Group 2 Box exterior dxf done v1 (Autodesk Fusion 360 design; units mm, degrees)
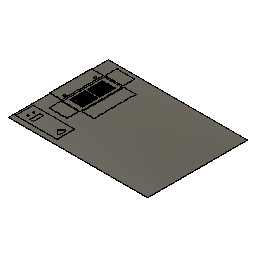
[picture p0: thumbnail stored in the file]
sketch "草图1" plane through (0, 0, 0) normal (0, 0, 1) x axis (1, 0, 0)
  line L1 (-60, 148.5) -> (60, 148.5)
  line L2 (-60, -148.5) -> (-60, 148.5)
  line L3 (60, -148.5) -> (-60, -148.5)
  line L4 (60, 148.5) -> (60, -148.5)
  line L5 (-60, -148.5) -> (60, 148.5)
  line L6 (60, -148.5) -> (-60, 148.5)
  line L7 (-63, 151.5) -> (63, 151.5)
  line L8 (-63, -151.5) -> (-63, 151.5)
  line L9 (63, -151.5) -> (-63, -151.5)
  line L10 (63, 151.5) -> (63, -151.5)
  point P6 (0, 0)
  point P1 (0, 0)
  point P4 (-60, -148.5)
  point P5 (60, -148.5)
  point P3 (-60, 148.5)
  horizontal L1
  perpendicular L1 L2
  parallel L1 L3
  parallel L2 L4
  coincident L5 P6
  coincident L6 P6
  coincident P1 P6
  dimension "d1" distance P4 P5 = 120
  dimension "d2" distance P3 P4 = 297
  dimension "d3" = 3
extrude "拉伸1" new body sketch "草图1" profile of L1 L2 L3 L4 L7 L8 L9 L10 along normal blind 83
sketch "草图2" plane through (0, 0, 0) normal (0, 0, 1) x axis (1, 0, 0)
  line L1 (-63, -151.5) -> (63, -151.5)
  line L2 (-63, 151.5) -> (-63, -151.5)
  line L3 (63, 151.5) -> (-63, 151.5)
  line L4 (63, -151.5) -> (63, 151.5)
  horizontal L1
  vertical L2
  horizontal L3
  vertical L4
extrude "拉伸2" add sketch "草图2" against normal blind 3
sketch "草图1" plane through (0, 0, 0) normal (0, 0, 1) x axis (1, 0, 0)
  line L1 (-60, -151.5) -> (63, -151.5)
  line L2 (-62.9999, 151.5267) -> (-62.9999, -151.5)
  line L3 (63, 151.5267) -> (-59.9999, 151.5267)
  line L4 (63, -9.9866) -> (64, -9.9866)
  line L5 (64, 10.0134) -> (63, 10.0134)
  line L6 (66, -7.9866) -> (66, 8.0134)
  line L7 (60, 10.0134) -> (66, -9.9866)
  line L8 (66, 10.0134) -> (60, -9.9866)
  line L9 (63, 10.0134) -> (63, 151.5267)
  line L10 (63, -151.5) -> (63, -9.9866)
  line L11 (-59.9999, 156.5267) -> (-59.9999, 151.5267)
  line L12 (-62.9999, 156.5267) -> (-59.9999, 156.5267)
  line L13 (-62.9999, 151.5267) -> (-62.9999, 156.5267)
  line L14 (-62.9999, -151.5) -> (-63, -151.5)
  line L15 (-60, -156.5) -> (-60, -151.5)
  line L16 (-63, -156.5) -> (-60, -156.5)
  line L17 (-63, -151.5) -> (-63, -156.5)
  arc A1 centre (64, -7.9866) radius 2 clockwise from (66, -7.9866) to (64, -9.9866)
  arc A2 centre (64, 8.0134) radius 2 clockwise from (64, 10.0134) to (66, 8.0134)
  point P6 (66, -9.9866)
  point P9 (66, 10.0134)
  point P16 (63, -9.9866)
  point P8 (60, 10.0134)
  point P7 (60, -9.9866)
  point P4 (-62.9999, 151.5267)
  point P18 (-59.9999, 151.5267)
  point P20 (-62.9999, 156.5267)
  point P21 (-63, -151.5)
  point P22 (-60, -151.5)
  point P24 (-63, -156.5)
  horizontal L1
  vertical L2
  horizontal L3
  vertical L9
  horizontal L4
  parallel L4 L5
  coincident P6 L4
  coincident P6 L6
  tangent L4 A1
  tangent L6 A1
  coincident P9 L6
  coincident P9 L5
  tangent L6 A2
  tangent L5 A2
  coincident P16 L9
  collinear L9 L10
  vertical L11
  horizontal L12
  vertical L13
  horizontal L14
  vertical L15
  horizontal L16
  vertical L17
  dimension "d8" distance P8 P9 = 6
  dimension "d9" distance P7 P8 = 20
  dimension "d10" radius A1 = 2
  dimension "d11" radius A2 = 2
  dimension "d12" distance P4 P18 = 3
  dimension "d13" distance P4 P20 = 5
  dimension "d14" distance P21 P22 = 3
  dimension "d15" distance P21 P24 = 5
extrude "拉伸1" new body sketch "草图1" profile of L1 L2 L3 L10 L4 L5 L6 A1 A2 L11 L12 L13 L14 L15 L16 L17 along normal blind 3
move "移动1"
component_from_bodies "实体->零部件"
sketch "草图2" plane through (0, 0, 65) normal (0, 0, -1) x axis (1, 0, 0)
  line L1 (63, 9.9866) -> (64, 9.9866)
  line L2 (63, 151.5) -> (63, 9.9866)
  line L3 (-60, 151.5) -> (63, 151.5)
  line L4 (-60, 156.5) -> (-60, 151.5)
  line L5 (-63, 156.5) -> (-60, 156.5)
  line L6 (-63, 151.5) -> (-63, 156.5)
  line L7 (-62.9999, 151.5) -> (-63, 151.5)
  line L8 (-62.9999, -156.5267) -> (-62.9999, 151.5)
  line L9 (-59.9999, -156.5267) -> (-62.9999, -156.5267)
  line L10 (-59.9999, -151.5267) -> (-59.9999, -156.5267)
  line L11 (63, -151.5267) -> (-59.9999, -151.5267)
  line L12 (63, -10.0134) -> (63, -151.5267)
  line L13 (64, -10.0134) -> (63, -10.0134)
  line L14 (66, 7.9866) -> (66, -8.0134)
  arc A1 centre (64, 7.9866) radius 2 clockwise from (64, 9.9866) to (66, 7.9866)
  arc A2 centre (64, -8.0134) radius 2 clockwise from (66, -8.0134) to (64, -10.0134)
sketch "草图3" plane through (0, 0, 0) normal (0, 0, 1) x axis (1, 0, 0)
  line L1 (-1.3407, -91.6748) -> (-29.625, -119.959)
  line L2 (-1.3407, -91.6748) -> (26.9436, -119.959)
  arc A1 centre (-1.3407, -91.6748) radius 40 clockwise from (26.9436, -119.959) to (-29.625, -119.959)
  perpendicular L1 L2
  dimension "d19" diameter A1 = 80
split "分割1"
sketch "草图4" plane through (0, 0, 0) normal (0, 0, 1) x axis (1, 0, 0)
  line L1 (36.5, 73) -> (-36.5, 73)
  line L2 (36.5, 47) -> (36.5, 73)
  line L3 (-36.5, 47) -> (36.5, 47)
  line L4 (-36.5, 73) -> (-36.5, 47)
  line L5 (36.5, 47) -> (-36.5, 73)
  line L6 (-36.5, 47) -> (36.5, 73)
  circle C1 centre (20.9238, 102.4465) radius 6
  circle C2 centre (-20.0762, 102.4465) radius 6
  point P6 (0, 60)
  point P4 (36.5, 47)
  point P5 (-36.5, 47)
  point P3 (36.5, 73)
  horizontal L1
  perpendicular L1 L2
  parallel L1 L3
  parallel L2 L4
  coincident L5 P6
  coincident L6 P6
  dimension "d22" distance P4 P5 = 73
  dimension "d23" distance P3 P4 = 26
  dimension "d24" diameter C1 = 12
  dimension "d25" diameter C2 = 12
extrude "拉伸3" new body sketch "草图4" profile of L1 L2 L3 L4 C1 C2 along normal blind 5
move "移动3"
ground "地面1"
move "移动4"
split "分割2"
split "分割3"
ground "地面2"
hole "孔1" HoleDepth 15 HoleDiameter 15 TipAngle 118
remove_body "移除实体1"
remove_body "移除实体2"
remove_body "移除实体3"
ground "地面3"
sketch "草图3" plane through (63, 0, 0) normal (1, 0, 0) x axis (0, 1, 0)
  line L1 (151.5, 83) -> (151.5, 0)
  line L2 (-151.5, 83) -> (151.5, 83)
  line L3 (-151.5, -3) -> (-151.5, 83)
  line L4 (151.5, -3) -> (-151.5, -3)
  line L5 (151.5, 0) -> (151.5, -3)
  line L6 (-9, 80) -> (9, 80)
  line L7 (-10, 83) -> (-10, 81)
  line L8 (10, 81) -> (10, 83)
  arc A1 centre (-9, 81) radius 1 clockwise from (-9, 80) to (-10, 81)
  arc A2 centre (9, 81) radius 1 clockwise from (10, 81) to (9, 80)
  point P7 (0, 83)
  point P14 (-10, 83)
  point P15 (10, 83)
  horizontal L6
  perpendicular L6 L7
  parallel L7 L8
  midpoint L2 P7
  tangent L7 A1
  tangent L6 A1
  tangent L6 A2
  tangent L8 A2
  equal A1 A2
  coincident L2 P14
  coincident L2 P15
  dimension "d36" radius A1 = 1
ground "地面4"
position "位置"
extrude "拉伸3" cut sketch "草图3" profile of L2 L6 L7 L8 A1 A2 against normal blind 5
offset_faces "偏移面1" distance 3
offset_faces "偏移面2" distance -3
offset_faces "偏移面1" distance -3
offset_faces "偏移面2" distance -3
offset_faces "偏移面3" distance -3
offset_faces "偏移面4" distance -3
offset_faces "偏移面3" distance 3
offset_faces "偏移面4" distance -3
sketch "草图4" plane through (0, 0, 83) normal (0, 0, 1) x axis (-1, 0, 0)
  line L1 (-63, 10) -> (-66, 10)
  line L2 (-63, 148.5) -> (-63, 10)
  line L3 (63, 148.5) -> (-63, 148.5)
  line L4 (63, -148.5) -> (63, 148.5)
  line L5 (-63, -148.5) -> (63, -148.5)
  line L6 (-63, -10) -> (-63, -148.5)
  line L7 (-66, -10) -> (-63, -10)
  line L8 (-66, -151.5) -> (-66, -10)
  line L9 (66, -151.5) -> (-66, -151.5)
  line L10 (66, 151.5) -> (66, -151.5)
  line L11 (-66, 151.5) -> (66, 151.5)
  line L12 (-66, 10) -> (-66, 151.5)
  line L13 (57.0003, -151.5) -> (59.9995, -151.5)
  line L14 (57.0003, -148.5275) -> (57.0003, -151.5)
  line L15 (59.9995, -148.5275) -> (57.0003, -148.5275)
  line L16 (59.9995, -151.5) -> (59.9995, -148.5275)
  point P14 (59.9995, -151.5)
  horizontal L13
  vertical L14
  horizontal L15
  vertical L16
  coincident L9 P14
extrude "拉伸4" add sketch "草图4" profile of L9 L13 L14 L15 L16 along normal blind 6.1
sketch "草图5" plane through (-59.9995, 0, 0) normal (-1, 0, 0) x axis (0, -1, 0)
  line L1 (-148.5275, 83) -> (-151.5, 83)
  line L2 (-148.5275, 89.1) -> (-148.5275, 83)
  line L3 (-151.5, 89.1) -> (-148.5275, 89.1)
  line L4 (-151.5, 83) -> (-151.5, 89.1)
  line L5 (-148.5275, 89.1) -> (-151.5, 89.1)
  line L6 (-148.5275, 86.05) -> (-148.5275, 89.1)
  line L7 (-151.5, 86.05) -> (-148.5275, 86.05)
  line L8 (-151.5, 89.1) -> (-151.5, 86.05)
  point P8 (-148.5275, 86.05)
  point P5 (-151.5, 89.1)
  point P6 (-151.5, 89.1)
  horizontal L5
  vertical L6
  horizontal L7
  vertical L8
  midpoint L2 P8
  coincident P5 P6
extrude "拉伸5" add sketch "草图5" profile of L2 L3 L4 L5 L6 L7 L8 along normal blind 6
sketch "草图6" plane through (0, 0, 83) normal (0, 0, 1) x axis (-1, 0, 0)
  line L1 (57.0003, -148.5275) -> (57.0003, -151.5)
  line L2 (59.9995, -148.5275) -> (57.0003, -148.5275)
  line L3 (59.9995, -151.5) -> (59.9995, -148.5275)
  line L4 (66, -151.5) -> (59.9995, -151.5)
  line L5 (66, 151.5) -> (66, -151.5)
  line L6 (-66, 151.5) -> (66, 151.5)
  line L7 (-66, 10) -> (-66, 151.5)
  line L8 (-63, 10) -> (-66, 10)
  line L9 (-63, 148.5) -> (-63, 10)
  line L10 (63, 148.5) -> (-63, 148.5)
  line L11 (63, -148.5) -> (63, 148.5)
  line L12 (-63, -148.5) -> (63, -148.5)
  line L13 (-63, -10) -> (-63, -148.5)
  line L14 (-66, -10) -> (-63, -10)
  line L15 (-66, -151.5) -> (-66, -10)
  line L16 (57.0003, -151.5) -> (-66, -151.5)
  line L17 (63, -151.5) -> (66, -151.5)
  line L18 (63, -148.5) -> (63, -151.5)
  line L19 (66, -148.5) -> (63, -148.5)
  line L20 (66, -151.5) -> (66, -148.5)
  point P6 (66, -151.5)
  point P18 (66, -151.5)
  point P19 (63, -151.5)
  point P21 (66, -148.5)
  horizontal L17
  vertical L18
  horizontal L19
  vertical L20
  coincident P6 P18
  dimension "d51" distance P18 P19 = 3
  dimension "d52" distance P18 P21 = 3
extrude "拉伸6" add sketch "草图6" profile of L4 L5 L17 L18 L19 L20 along normal blind 3
sketch "草图7" plane through (0, 0, 83) normal (0, 0, 1) x axis (-1, 0, 0)
  line L1 (66, -148.5) -> (63, -148.5)
  line L2 (66, 151.5) -> (66, -148.5)
  line L3 (-66, 151.5) -> (66, 151.5)
  line L4 (-66, 10) -> (-66, 151.5)
  line L5 (-63, 10) -> (-66, 10)
  line L6 (-63, 148.5) -> (-63, 10)
  line L7 (63, 148.5) -> (-63, 148.5)
  line L8 (63, -148.5) -> (63, 148.5)
  line L9 (57, 148.5) -> (66, 148.5)
  line L10 (57, 151.5) -> (57, 148.5)
  line L11 (66, 151.5) -> (57, 151.5)
  line L12 (66, 148.5) -> (66, 151.5)
  point P10 (66, 148.5)
  point P11 (57, 148.5)
  horizontal L9
  vertical L10
  horizontal L11
  vertical L12
  coincident L2 P10
  dimension "d55" distance P10 P11 = 9
extrude "拉伸7" add sketch "草图7" profile of L2 L3 L7 L9 L10 L11 L12 along normal blind 6
sketch "草图8" plane through (0, -151.5, 0) normal (0, -1, 0) x axis (1, 0, 0)
  line L1 (66, 83) -> (66, -3)
  line L2 (-57, 83) -> (66, 83)
  line L3 (-57, 89) -> (-57, 83)
  line L4 (-66, 89) -> (-57, 89)
  line L5 (-66, -3) -> (-66, 89)
  line L6 (66, -3) -> (-66, -3)
  circle C1 centre (-61.5, 81.5) radius 2.15
  dimension "d58" diameter C1 = 4.3
extrude "拉伸1" cut sketch "草图8" profile of C1 along normal blind 38
extrude "拉伸8" cut sketch "草图8" profile of C1 against normal blind 318
hole "孔1" HoleDepth 27.5 HoleDiameter 15 TipAngle 118 CBDepth 25 CBDiameter 16.5
hole "孔2" HoleDepth 27.5 HoleDiameter 15 TipAngle 118 CBDepth 1 CBDiameter 16.5
offset_faces "偏移面5" distance 3
sketch "草图9" plane through (0, 0, -3) normal (0, 0, -1) x axis (1, 0, 0)
  line L1 (66, -151.5) -> (-66, -151.5)
  line L2 (66, 151.5) -> (66, -151.5)
  line L3 (-66, 151.5) -> (66, 151.5)
  line L4 (-66, -151.5) -> (-66, 151.5)
  line L5 (-36, -151.5) -> (-66, -151.5)
  line L6 (-36, -148.5) -> (-36, -151.5)
  line L7 (-66, -148.5) -> (-36, -148.5)
  line L8 (-66, -151.5) -> (-66, -148.5)
  line L9 (36, -151.5) -> (66, -151.5)
  line L10 (36, -148.5) -> (36, -151.5)
  line L11 (66, -148.5) -> (36, -148.5)
  line L12 (66, -151.5) -> (66, -148.5)
  line L13 (-14, -151.5) -> (10.9264, -151.5)
  line L14 (-14, -148.5) -> (-14, -151.5)
  line L15 (10.9264, -148.5) -> (-14, -148.5)
  line L16 (10.9264, -151.5) -> (10.9264, -148.5)
  point P2 (-66, -151.5)
  point P6 (-66, -151.5)
  point P3 (66, -151.5)
  point P10 (66, -151.5)
  point P7 (-36, -151.5)
  point P9 (-66, -148.5)
  point P11 (36, -151.5)
  point P13 (66, -148.5)
  horizontal L5
  vertical L6
  horizontal L7
  vertical L8
  coincident P2 P6
  horizontal L9
  vertical L10
  horizontal L11
  vertical L12
  coincident P3 P10
  horizontal L13
  vertical L14
  horizontal L15
  vertical L16
  dimension "d74" distance P6 P7 = 30
  dimension "d75" distance P6 P9 = 3
  dimension "d76" distance P10 P11 = 30
  dimension "d77" distance P10 P13 = 3
sketch "草图10" plane through (66, 0, 0) normal (1, 0, 0) x axis (0, 1, 0)
  line L1 (-10, 83) -> (-10, 81)
  line L2 (-151.5, -3) -> (-151.5, 83)
  line L3 (151.5, -3) -> (-151.5, -3)
  line L4 (151.5, 83) -> (151.5, -3)
  line L5 (10, 83) -> (151.5, 83)
  line L6 (10, 81) -> (10, 83)
  line L7 (-9, 80) -> (9, 80)
  line L8 (-148.5, 92) -> (-148.5, 83)
  arc A1 centre (9, 81) radius 1 clockwise from (10, 81) to (9, 80)
  arc A2 centre (-9, 81) radius 1 clockwise from (-9, 80) to (-10, 81)
  point P4 (-151.5, 83)
  point P14 (-148.5, 83)
  vertical L8
  dimension "d79" distance P4 P14 = 3
split "分割1"
sketch "草图11" plane through (66, 0, 0) normal (1, 0, 0) x axis (0, 1, 0)
  line L1 (-148.5, -3) -> (-148.5, 83)
  line L2 (151.5, -3) -> (-148.5, -3)
  line L3 (151.5, 83) -> (151.5, -3)
  line L4 (10, 83) -> (151.5, 83)
  line L5 (10, 81) -> (10, 83)
  line L6 (-9, 80) -> (9, 80)
  line L7 (-10, 83) -> (-10, 81)
  line L8 (-148.5, 83) -> (-10, 83)
  line L9 (148.5, 93) -> (148.5, 83)
  arc A1 centre (9, 81) radius 1 clockwise from (10, 81) to (9, 80)
  arc A2 centre (-9, 81) radius 1 clockwise from (-9, 80) to (-10, 81)
  point P5 (151.5, 83)
  point P14 (148.5, 83)
  vertical L9
  dimension "d81" distance P5 P14 = 3
split "分割2"
sketch "草图12" plane through (0, -148.5, 0) normal (0, -1, 0) x axis (1, 0, 0)
  line L1 (66, -3) -> (-66, -3)
  line L2 (66, 83) -> (66, -3)
  line L3 (63, 83) -> (66, 83)
  line L4 (63, 0) -> (63, 83)
  line L5 (-63, 0) -> (63, 0)
  line L6 (-63, 79.9597) -> (-63, 0)
  line L7 (-66, 83) -> (-63.0403, 83)
  line L8 (-66, -3) -> (-66, 83)
  line L9 (-66, 0) -> (-73, 0)
  arc A1 centre (-61.5, 81.5) radius 2.15 clockwise from (-63, 79.9597) to (-63.0403, 83)
  point P2 (-66, -3)
  point P13 (-66, 0)
  horizontal L9
  dimension "d84" distance P2 P13 = 3
split "分割3"
sketch "草图13" plane through (0, 0, 0) normal (0, 0, 1) x axis (1, 0, 0)
  line L1 (-45.1733, 122.4619) -> (-47.2908, 122.4619)
  line L2 (-45.1733, 8.8229) -> (-45.1733, 122.4619)
  line L3 (-47.2908, 8.8229) -> (-45.1733, 8.8229)
  line L4 (-47.2908, 122.4619) -> (-47.2908, 8.8229)
  line L5 (-37.2908, 122.4619) -> (-37.2908, 8.8229)
  line L6 (-35.1733, 8.8229) -> (-35.1733, 122.4619)
  line L7 (-35.1733, 122.4619) -> (-37.2908, 122.4619)
  line L8 (-37.2908, 8.8229) -> (-35.1733, 8.8229)
  line L9 (-27.2908, 122.4619) -> (-27.2908, 8.8229)
  line L10 (-25.1733, 8.8229) -> (-25.1733, 122.4619)
  line L11 (-25.1733, 122.4619) -> (-27.2908, 122.4619)
  line L12 (-27.2908, 8.8229) -> (-25.1733, 8.8229)
  line L13 (-17.2908, 122.4619) -> (-17.2908, 8.8229)
  line L14 (-15.1733, 8.8229) -> (-15.1733, 122.4619)
  line L15 (-15.1733, 122.4619) -> (-17.2908, 122.4619)
  line L16 (-17.2908, 8.8229) -> (-15.1733, 8.8229)
  line L17 (-7.2908, 122.4619) -> (-7.2908, 8.8229)
  line L18 (-5.1733, 8.8229) -> (-5.1733, 122.4619)
  line L19 (-5.1733, 122.4619) -> (-7.2908, 122.4619)
  line L20 (-7.2908, 8.8229) -> (-5.1733, 8.8229)
  line L21 (2.7092, 122.4619) -> (2.7092, 8.8229)
  line L22 (4.8267, 8.8229) -> (4.8267, 122.4619)
  line L23 (4.8267, 122.4619) -> (2.7092, 122.4619)
  line L24 (2.7092, 8.8229) -> (4.8267, 8.8229)
  line L25 (12.7092, 122.4619) -> (12.7092, 8.8229)
  line L26 (14.8267, 8.8229) -> (14.8267, 122.4619)
  line L27 (14.8267, 122.4619) -> (12.7092, 122.4619)
  line L28 (12.7092, 8.8229) -> (14.8267, 8.8229)
  line L29 (22.7092, 122.4619) -> (22.7092, 8.8229)
  line L30 (24.8267, 8.8229) -> (24.8267, 122.4619)
  line L31 (24.8267, 122.4619) -> (22.7092, 122.4619)
  line L32 (22.7092, 8.8229) -> (24.8267, 8.8229)
  line L33 (32.7092, 122.4619) -> (32.7092, 8.8229)
  line L34 (34.8267, 8.8229) -> (34.8267, 122.4619)
  line L35 (34.8267, 122.4619) -> (32.7092, 122.4619)
  line L36 (32.7092, 8.8229) -> (34.8267, 8.8229)
  line L37 (42.7092, 122.4619) -> (42.7092, 8.8229)
  line L38 (44.8267, 8.8229) -> (44.8267, 122.4619)
  line L39 (44.8267, 122.4619) -> (42.7092, 122.4619)
  line L40 (42.7092, 8.8229) -> (44.8267, 8.8229)
  line L41 (-47.2908, 122.4619) -> (-47.2908, 8.8229)
  line L42 (-45.1733, 8.8229) -> (-45.1733, 122.4619)
  line L43 (-45.1733, 122.4619) -> (-47.2908, 122.4619)
  line L44 (-47.2908, 8.8229) -> (-45.1733, 8.8229)
  line L45 (-17.2908, -2.5381) -> (-17.2908, -116.1771)
  line L46 (-27.2908, -116.1771) -> (-25.1733, -116.1771)
  line L47 (-47.2908, -116.1771) -> (-45.1733, -116.1771)
  line L48 (-5.1733, -2.5381) -> (-7.2908, -2.5381)
  line L49 (32.7092, -116.1771) -> (34.8267, -116.1771)
  line L50 (42.7092, -2.5381) -> (42.7092, -116.1771)
  line L51 (-5.1733, -116.1771) -> (-5.1733, -2.5381)
  line L52 (4.8267, -116.1771) -> (4.8267, -2.5381)
  line L53 (-35.1733, -2.5381) -> (-37.2908, -2.5381)
  line L54 (-37.2908, -2.5381) -> (-37.2908, -116.1771)
  line L55 (2.7092, -116.1771) -> (4.8267, -116.1771)
  line L56 (32.7092, -2.5381) -> (32.7092, -116.1771)
  line L57 (-27.2908, -2.5381) -> (-27.2908, -116.1771)
  line L58 (-25.1733, -116.1771) -> (-25.1733, -2.5381)
  line L59 (-47.2908, -2.5381) -> (-47.2908, -116.1771)
  line L60 (4.8267, -2.5381) -> (2.7092, -2.5381)
  line L61 (34.8267, -116.1771) -> (34.8267, -2.5381)
  line L62 (-17.2908, -116.1771) -> (-15.1733, -116.1771)
  line L63 (-45.1733, -2.5381) -> (-47.2908, -2.5381)
  line L64 (-35.1733, -116.1771) -> (-35.1733, -2.5381)
  line L65 (44.8267, -2.5381) -> (42.7092, -2.5381)
  line L66 (-25.1733, -2.5381) -> (-27.2908, -2.5381)
  line L67 (12.7092, -2.5381) -> (12.7092, -116.1771)
  line L68 (-15.1733, -2.5381) -> (-17.2908, -2.5381)
  line L69 (24.8267, -116.1771) -> (24.8267, -2.5381)
  line L70 (-7.2908, -116.1771) -> (-5.1733, -116.1771)
  line L71 (42.7092, -116.1771) -> (44.8267, -116.1771)
  line L72 (-45.1733, -116.1771) -> (-45.1733, -2.5381)
  line L73 (2.7092, -2.5381) -> (2.7092, -116.1771)
  line L74 (22.7092, -2.5381) -> (22.7092, -116.1771)
  line L75 (44.8267, -116.1771) -> (44.8267, -2.5381)
  line L76 (-15.1733, -116.1771) -> (-15.1733, -2.5381)
  line L77 (34.8267, -2.5381) -> (32.7092, -2.5381)
  line L78 (-47.2908, -2.5381) -> (-47.2908, -116.1771)
  line L79 (-45.1733, -2.5381) -> (-47.2908, -2.5381)
  line L80 (14.8267, -116.1771) -> (14.8267, -2.5381)
  line L81 (14.8267, -2.5381) -> (12.7092, -2.5381)
  line L82 (-7.2908, -2.5381) -> (-7.2908, -116.1771)
  line L83 (-37.2908, -116.1771) -> (-35.1733, -116.1771)
  line L84 (12.7092, -116.1771) -> (14.8267, -116.1771)
  line L85 (-47.2908, -116.1771) -> (-45.1733, -116.1771)
  line L86 (-45.1733, -116.1771) -> (-45.1733, -2.5381)
  line L87 (22.7092, -116.1771) -> (24.8267, -116.1771)
  line L88 (24.8267, -2.5381) -> (22.7092, -2.5381)
  horizontal L1
  vertical L2
  horizontal L3
  vertical L4
  horizontal L7
  vertical L6
  horizontal L8
  vertical L5
  horizontal L11
  vertical L10
  horizontal L12
  vertical L9
  horizontal L15
  vertical L14
  horizontal L16
  vertical L13
  horizontal L19
  vertical L18
  horizontal L20
  vertical L17
  horizontal L23
  vertical L22
  horizontal L24
  vertical L21
  horizontal L27
  vertical L26
  horizontal L28
  vertical L25
  horizontal L31
  vertical L30
  horizontal L32
  vertical L29
  horizontal L35
  vertical L34
  horizontal L36
  vertical L33
  horizontal L39
  vertical L38
  horizontal L40
  vertical L37
  horizontal L43
  vertical L42
  horizontal L44
  vertical L41
  horizontal L63
  vertical L72
  horizontal L47
  vertical L59
  horizontal L53
  vertical L64
  horizontal L83
  vertical L54
  horizontal L66
  vertical L58
  horizontal L46
  vertical L57
  horizontal L68
  vertical L76
  horizontal L62
  vertical L45
  horizontal L48
  vertical L51
  horizontal L70
  vertical L82
  horizontal L60
  vertical L52
  horizontal L55
  vertical L73
  horizontal L81
  vertical L80
  horizontal L84
  vertical L67
  horizontal L88
  vertical L69
  horizontal L87
  vertical L74
  horizontal L77
  vertical L61
  horizontal L49
  vertical L56
  horizontal L65
  vertical L75
  horizontal L71
  vertical L50
  horizontal L79
  vertical L86
  horizontal L85
  vertical L78
extrude "拉伸9" cut sketch "草图13" against normal blind 5
extrude "拉伸10" cut sketch "草图9" profile of L1 L4 L5 L6 L7 L8 against normal blind 3
extrude "拉伸11" cut sketch "草图9" profile of L1 L13 L14 L15 L16 against normal blind 3
extrude "拉伸12" cut sketch "草图9" profile of L1 L2 L9 L10 L11 L12 against normal blind 3
extrude "拉伸13" new body sketch "草图9" profile of L1 L2 L4 L5 L6 L7 L8 L9 L10 L11 L12 L13 L14 L15 L16 against normal blind 3
combine "合并1"
sketch "草图14" plane through (0, 0, -3) normal (0, 0, -1) x axis (1, 0, 0)
  line L1 (66, 148.5) -> (-66, 148.5)
  line L2 (66, 151.5) -> (66, 148.5)
  line L3 (-66, 151.5) -> (66, 151.5)
  line L4 (-66, 148.5) -> (-66, 151.5)
  line L5 (-36, 151.5) -> (-66, 151.5)
  line L6 (-36, 148.5) -> (-36, 151.5)
  line L7 (-66, 148.5) -> (-36, 148.5)
  line L8 (-66, 151.5) -> (-66, 148.5)
  line L9 (36, 151.5) -> (36, 148.5)
  line L10 (66, 151.5) -> (36, 151.5)
  line L11 (66, 148.5) -> (66, 151.5)
  line L12 (36, 148.5) -> (66, 148.5)
  line L13 (-15, 151.5) -> (-15, 148.5)
  line L14 (15, 151.5) -> (-15, 151.5)
  line L15 (15, 148.5) -> (15, 151.5)
  line L16 (-15, 148.5) -> (15, 148.5)
  point P5 (-66, 151.5)
  point P6 (-66, 151.5)
  point P7 (-36, 151.5)
  point P9 (-66, 148.5)
  point P12 (36, 151.5)
  point P13 (66, 151.5)
  point P10 (36, 148.5)
  point P16 (-15, 151.5)
  point P17 (15, 151.5)
  point P14 (-15, 148.5)
  horizontal L5
  vertical L6
  horizontal L7
  vertical L8
  coincident P5 P6
  horizontal L10
  vertical L11
  horizontal L12
  vertical L9
  horizontal L14
  vertical L15
  horizontal L16
  vertical L13
  dimension "d95" distance P6 P7 = 30
  dimension "d96" distance P6 P9 = 3
  dimension "d97" distance P12 P13 = 30
  dimension "d98" distance P10 P12 = 3
  dimension "d99" distance P16 P17 = 30
  dimension "d100" distance P14 P16 = 3
extrude "拉伸14" cut sketch "草图14" against normal blind 3
extrude "拉伸15" new body sketch "草图14" against normal blind 3
combine "合并2"
sketch "草图15" plane through (0, 0, -3) normal (0, 0, -1) x axis (1, 0, 0)
  line L1 (24.8267, 116.1771) -> (22.7092, 116.1771)
  line L2 (24.8267, 2.5381) -> (24.8267, 116.1771)
  line L3 (22.7092, 2.5381) -> (24.8267, 2.5381)
  line L4 (22.7092, 116.1771) -> (22.7092, 2.5381)
  line L5 (2.7092, -122.4619) -> (4.8267, -122.4619)
  line L6 (2.7092, -8.8229) -> (2.7092, -122.4619)
  line L7 (4.8267, -8.8229) -> (2.7092, -8.8229)
  line L8 (4.8267, -122.4619) -> (4.8267, -8.8229)
  line L9 (-37.2908, -122.4619) -> (-35.1733, -122.4619)
  line L10 (-37.2908, -8.8229) -> (-37.2908, -122.4619)
  line L11 (-35.1733, -8.8229) -> (-37.2908, -8.8229)
  line L12 (-35.1733, -122.4619) -> (-35.1733, -8.8229)
  line L13 (42.7092, 116.1771) -> (42.7092, 2.5381)
  line L14 (44.8267, 116.1771) -> (42.7092, 116.1771)
  line L15 (44.8267, 2.5381) -> (44.8267, 116.1771)
  line L16 (42.7092, 2.5381) -> (44.8267, 2.5381)
  line L17 (22.7092, -122.4619) -> (24.8267, -122.4619)
  line L18 (22.7092, -8.8229) -> (22.7092, -122.4619)
  line L19 (24.8267, -8.8229) -> (22.7092, -8.8229)
  line L20 (24.8267, -122.4619) -> (24.8267, -8.8229)
  line L21 (-25.1733, 116.1771) -> (-27.2908, 116.1771)
  line L22 (-25.1733, 2.5381) -> (-25.1733, 116.1771)
  line L23 (-27.2908, 2.5381) -> (-25.1733, 2.5381)
  line L24 (-27.2908, 116.1771) -> (-27.2908, 2.5381)
  line L25 (32.7092, -122.4619) -> (34.8267, -122.4619)
  line L26 (32.7092, -8.8229) -> (32.7092, -122.4619)
  line L27 (34.8267, -8.8229) -> (32.7092, -8.8229)
  line L28 (34.8267, -122.4619) -> (34.8267, -8.8229)
  line L29 (4.8267, 2.5381) -> (4.8267, 116.1771)
  line L30 (2.7092, 2.5381) -> (4.8267, 2.5381)
  line L31 (2.7092, 116.1771) -> (2.7092, 2.5381)
  line L32 (4.8267, 116.1771) -> (2.7092, 116.1771)
  line L33 (-7.2908, -122.4619) -> (-5.1733, -122.4619)
  line L34 (-7.2908, -8.8229) -> (-7.2908, -122.4619)
  line L35 (-5.1733, -8.8229) -> (-7.2908, -8.8229)
  line L36 (-5.1733, -122.4619) -> (-5.1733, -8.8229)
  line L37 (-47.2908, 116.1771) -> (-47.2908, 2.5381)
  line L38 (-45.1733, 116.1771) -> (-47.2908, 116.1771)
  line L39 (-45.1733, 2.5381) -> (-45.1733, 116.1771)
  line L40 (-47.2908, 2.5381) -> (-45.1733, 2.5381)
  line L41 (-17.2908, -122.4619) -> (-15.1733, -122.4619)
  line L42 (-17.2908, -8.8229) -> (-17.2908, -122.4619)
  line L43 (-15.1733, -8.8229) -> (-17.2908, -8.8229)
  line L44 (-15.1733, -122.4619) -> (-15.1733, -8.8229)
  line L45 (-17.2908, 116.1771) -> (-17.2908, 2.5381)
  line L46 (-15.1733, 116.1771) -> (-17.2908, 116.1771)
  line L47 (-15.1733, 2.5381) -> (-15.1733, 116.1771)
  line L48 (-17.2908, 2.5381) -> (-15.1733, 2.5381)
  line L49 (12.7092, -122.4619) -> (14.8267, -122.4619)
  line L50 (12.7092, -8.8229) -> (12.7092, -122.4619)
  line L51 (14.8267, -8.8229) -> (12.7092, -8.8229)
  line L52 (14.8267, -122.4619) -> (14.8267, -8.8229)
  line L53 (42.7092, -122.4619) -> (44.8267, -122.4619)
  line L54 (42.7092, -8.8229) -> (42.7092, -122.4619)
  line L55 (44.8267, -8.8229) -> (42.7092, -8.8229)
  line L56 (44.8267, -122.4619) -> (44.8267, -8.8229)
  line L57 (-37.2908, 2.5381) -> (-35.1733, 2.5381)
  line L58 (-37.2908, 116.1771) -> (-37.2908, 2.5381)
  line L59 (-35.1733, 116.1771) -> (-37.2908, 116.1771)
  line L60 (-35.1733, 2.5381) -> (-35.1733, 116.1771)
  line L61 (-47.2908, -122.4619) -> (-45.1733, -122.4619)
  line L62 (-47.2908, -8.8229) -> (-47.2908, -122.4619)
  line L63 (-45.1733, -8.8229) -> (-47.2908, -8.8229)
  line L64 (-45.1733, -122.4619) -> (-45.1733, -8.8229)
  line L65 (34.8267, 116.1771) -> (32.7092, 116.1771)
  line L66 (34.8267, 2.5381) -> (34.8267, 116.1771)
  line L67 (32.7092, 2.5381) -> (34.8267, 2.5381)
  line L68 (32.7092, 116.1771) -> (32.7092, 2.5381)
  line L69 (-5.1733, 2.5381) -> (-5.1733, 116.1771)
  line L70 (-7.2908, 2.5381) -> (-5.1733, 2.5381)
  line L71 (-7.2908, 116.1771) -> (-7.2908, 2.5381)
  line L72 (-5.1733, 116.1771) -> (-7.2908, 116.1771)
  line L73 (12.7092, 2.5381) -> (14.8267, 2.5381)
  line L74 (12.7092, 116.1771) -> (12.7092, 2.5381)
  line L75 (14.8267, 116.1771) -> (12.7092, 116.1771)
  line L76 (14.8267, 2.5381) -> (14.8267, 116.1771)
  line L77 (-27.2908, -122.4619) -> (-25.1733, -122.4619)
  line L78 (-27.2908, -8.8229) -> (-27.2908, -122.4619)
  line L79 (-25.1733, -8.8229) -> (-27.2908, -8.8229)
  line L80 (-25.1733, -122.4619) -> (-25.1733, -8.8229)
  line L81 (66, 151.5) -> (66, -148.5)
  line L82 (36, 151.5) -> (66, 151.5)
  line L83 (36, 148.5) -> (36, 151.5)
  line L84 (15, 148.5) -> (36, 148.5)
  line L85 (15, 151.5) -> (15, 148.5)
  line L86 (-15, 151.5) -> (15, 151.5)
  line L87 (-15, 148.5) -> (-15, 151.5)
  line L88 (-36, 148.5) -> (-15, 148.5)
  line L89 (-36, 151.5) -> (-36, 148.5)
  line L90 (-66, 151.5) -> (-36, 151.5)
  line L91 (-66, -148.5) -> (-66, 151.5)
  line L92 (-66, -151.5) -> (-66, -148.5)
  line L93 (-36, -151.5) -> (-66, -151.5)
  line L94 (-36, -148.5) -> (-36, -151.5)
  line L95 (-14, -148.5) -> (-36, -148.5)
  line L96 (-14, -151.5) -> (-14, -148.5)
  line L97 (10.9264, -151.5) -> (-14, -151.5)
  line L98 (10.9264, -148.5) -> (10.9264, -151.5)
  line L99 (36, -148.5) -> (10.9264, -148.5)
  line L100 (36, -151.5) -> (36, -148.5)
  line L101 (66, -151.5) -> (36, -151.5)
  line L102 (66, -148.5) -> (66, -151.5)
  line L103 (-63, 151.5) -> (-66, 151.5)
  line L104 (-63, 121.5) -> (-63, 151.5)
  line L105 (-66, 121.5) -> (-63, 121.5)
  line L106 (-66, 151.5) -> (-66, 121.5)
  line L107 (-63, 61.5) -> (-63, 91.5)
  line L108 (-66, 61.5) -> (-63, 61.5)
  line L109 (-66, 91.5) -> (-66, 61.5)
  line L110 (-63, 91.5) -> (-66, 91.5)
  line L111 (-63, -8.5) -> (-63, 21.5)
  line L112 (-66, -8.5) -> (-63, -8.5)
  line L113 (-66, 21.5) -> (-66, -8.5)
  line L114 (-63, 21.5) -> (-66, 21.5)
  line L115 (-63, -78.5) -> (-63, -48.5)
  line L116 (-66, -78.5) -> (-63, -78.5)
  line L117 (-66, -48.5) -> (-66, -78.5)
  line L118 (-63, -48.5) -> (-66, -48.5)
  line L119 (-63, -151.5) -> (-63, -121.5)
  line L120 (-66, -151.5) -> (-63, -151.5)
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  point P92 (-66, 151.5)
  point P104 (-66, 151.5)
  point P105 (-63, 151.5)
  point P107 (-66, 121.5)
  point P109 (-63, 91.5)
  point P110 (-66, 91.5)
  point P108 (-66, 61.5)
  point P113 (-63, 21.5)
  point P114 (-66, 21.5)
  point P112 (-66, -8.5)
  point P117 (-63, -48.5)
  point P118 (-66, -48.5)
  point P116 (-66, -78.5)
  point P121 (-63, -121.5)
  point P122 (-66, -121.5)
  point P120 (-66, -151.5)
  point P127 (66, 151.5)
  point P130 (63, 151.5)
  point P126 (63, 121.5)
  point P128 (63, 91.5)
  point P134 (66, 91.5)
  point P133 (63, 61.5)
  point P136 (66, 21.5)
  point P137 (63, 21.5)
  point P135 (63, -8.5)
  point P125 (66, -48.5)
  point P139 (63, -48.5)
  point P132 (63, -78.5)
  point P141 (66, -121.5)
  point P143 (63, -121.5)
  point P138 (63, -151.5)
  horizontal L103
  vertical L104
  horizontal L105
  vertical L106
  coincident P92 P104
  horizontal L110
  vertical L107
  horizontal L108
  vertical L109
  horizontal L114
  vertical L111
  horizontal L112
  vertical L113
  horizontal L118
  vertical L115
  horizontal L116
  vertical L117
  vertical L119
  horizontal L120
  dimension "d105" distance P104 P105 = 3
  dimension "d106" distance P104 P107 = 30
  dimension "d107" distance P109 P110 = 3
  dimension "d108" distance P108 P110 = 30
  dimension "d109" distance P113 P114 = 3
  dimension "d110" distance P112 P114 = 30
  dimension "d111" distance P117 P118 = 3
  dimension "d112" distance P116 P118 = 30
  dimension "d113" distance P121 P122 = 3
  dimension "d114" distance P120 P122 = 30
  dimension "d115" distance P127 P130 = 3
  dimension "d116" distance P126 P130 = 30
  dimension "d117" distance P128 P134 = 3
  dimension "d118" distance P128 P133 = 30
  dimension "d119" distance P136 P137 = 3
  dimension "d120" distance P135 P137 = 30
  dimension "d121" distance P125 P139 = 3
  dimension "d122" distance P132 P139 = 30
  dimension "d123" distance P141 P143 = 3
  dimension "d124" distance P138 P143 = 30
extrude "拉伸16" cut sketch "草图15" against normal blind 3
extrude "拉伸17" new body sketch "草图15" against normal blind 3
combine "合并3"
combine "合并4"
sketch "草图16" plane through (0, 151.5, 0) normal (0, 1, 0) x axis (-1, 0, 0)
  line L1 (-36, 0) -> (-66, 0)
  line L2 (-36, -3) -> (-36, 0)
  line L3 (-10.9264, -3) -> (-36, -3)
  line L4 (-10.9264, 0) -> (-10.9264, -3)
  line L5 (14, 0) -> (-10.9264, 0)
  line L6 (14, -3) -> (14, 0)
  line L7 (36, -3) -> (14, -3)
  line L8 (36, 0) -> (36, -3)
  line L9 (66, 0) -> (36, 0)
  line L10 (66, 86) -> (66, 0)
  line L11 (63, 86) -> (66, 86)
  line L12 (63, 83.0403) -> (63, 86)
  line L13 (59.9995, 86.05) -> (59.9995, 83.0399)
  line L14 (65.9995, 86.05) -> (59.9995, 86.05)
  line L15 (65.9995, 89.1) -> (65.9995, 86.05)
  line L16 (57.0003, 89.1) -> (65.9995, 89.1)
  line L17 (57.0003, 83) -> (57.0003, 89.1)
  line L18 (-66, 83) -> (57.0003, 83)
  line L19 (-66, 0) -> (-66, 83)
  line L20 (-63, 0) -> (-66, 0)
  line L21 (-63, 20) -> (-63, 0)
  line L22 (-66, 20) -> (-63, 20)
  line L23 (-66, 0) -> (-66, 20)
  line L24 (-66, 0) -> (-66, 20)
  line L25 (-63, 0) -> (-66, 0)
  line L26 (-63, 20) -> (-63, 0)
  line L27 (-66, 20) -> (-63, 20)
  line L28 (-66, 63) -> (-66, 83)
  line L29 (-63, 63) -> (-66, 63)
  line L30 (-63, 83) -> (-63, 63)
  line L31 (-66, 83) -> (-63, 83)
  line L32 (-66, 30) -> (-66, 50)
  line L33 (-63, 30) -> (-66, 30)
  line L34 (-63, 50) -> (-63, 30)
  line L35 (-66, 50) -> (-63, 50)
  line L36 (63, 30) -> (63, 50)
  line L37 (66, 30) -> (63, 30)
  line L38 (66, 50) -> (66, 30)
  line L39 (63, 50) -> (66, 50)
  line L40 (66, 66) -> (63, 66)
  line L41 (66, 77.8287) -> (66, 66)
  line L42 (63, 0) -> (63, 20)
  line L43 (66, 0) -> (63, 0)
  line L44 (63, 20) -> (66, 20)
  line L45 (66, 20) -> (66, 0)
  line L46 (63, 77.8287) -> (66, 77.8287)
  line L47 (63, 66) -> (63, 77.8287)
  arc A1 centre (61.5, 81.5) radius 2.15 clockwise from (63, 83.0403) to (59.9995, 83.0399)
  point P2 (-66, 0)
  point P23 (-66, 0)
  point P24 (-63, 0)
  point P26 (-66, 20)
  point P28 (-63, 0)
  point P30 (-66, 0)
  point P27 (-66, 20)
  point P32 (-63, 63)
  point P34 (-66, 63)
  point P31 (-66, 83)
  point P36 (-63, 30)
  point P38 (-66, 30)
  point P35 (-66, 50)
  point P47 (66, 0)
  point P49 (63, 0)
  point P41 (63, 20)
  point P40 (66, 66)
  point P43 (63, 66)
  point P13 (63, 86)
  point P45 (66, 30)
  point P46 (63, 30)
  point P44 (63, 50)
  horizontal L20
  vertical L21
  horizontal L22
  vertical L23
  coincident P2 P23
  horizontal L25
  vertical L26
  horizontal L27
  vertical L24
  horizontal L29
  vertical L30
  horizontal L31
  vertical L28
  horizontal L33
  vertical L34
  horizontal L35
  vertical L32
  horizontal L43
  vertical L45
  horizontal L44
  vertical L42
  horizontal L40
  vertical L41
  horizontal L37
  vertical L38
  horizontal L39
  vertical L36
  dimension "d129" distance P23 P24 = 3
  dimension "d130" distance P23 P26 = 20
  dimension "d131" distance P28 P30 = 3
  dimension "d132" distance P27 P30 = 20
  dimension "d133" distance P32 P34 = 3
  dimension "d134" distance P31 P34 = 20
  dimension "d135" distance P36 P38 = 3
  dimension "d136" distance P35 P38 = 20
  dimension "d137" distance P47 P49 = 3
  dimension "d138" distance P41 P49 = 20
  dimension "d139" distance P40 P43 = 3
  dimension "d140" distance P13 P43 = 20
  dimension "d141" distance P45 P46 = 3
  dimension "d142" distance P44 P46 = 20
extrude "拉伸18" cut sketch "草图16" profile of L1 L9 L10 L18 L19 L20 L21 L22 L23 L24 L25 L26 L27 L28 L29 L30 L31 L32 L33 L34 L35 L36 L37 L38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 against normal blind 3
extrude "拉伸19" new body sketch "草图16" profile of L1 L9 L10 L18 L19 L20 L21 L22 L23 L24 L25 L26 L27 L28 L29 L30 L31 L32 L33 L34 L35 L36 L37 L38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 against normal blind 3
combine "合并5"
sketch "草图17" plane through (0, -151.5, 0) normal (0, -1, 0) x axis (1, 0, 0)
  line L1 (-36, -3) -> (-36, 0)
  line L2 (-15, -3) -> (-36, -3)
  line L3 (-15, 0) -> (-15, -3)
  line L4 (15, 0) -> (-15, 0)
  line L5 (15, -3) -> (15, 0)
  line L6 (36, -3) -> (15, -3)
  line L7 (36, 0) -> (36, -3)
  line L8 (66, 0) -> (36, 0)
  line L9 (66, 83) -> (66, 0)
  line L10 (-57, 83) -> (66, 83)
  line L11 (-57, 89) -> (-57, 83)
  line L12 (-66, 89) -> (-57, 89)
  line L13 (-66, 0) -> (-66, 89)
  line L14 (-36, 0) -> (-66, 0)
  line L15 (-63, 77.9245) -> (-66, 77.9245)
  line L16 (-63, 66) -> (-63, 77.9245)
  line L17 (-66, 66) -> (-63, 66)
  line L18 (-66, 77.9245) -> (-66, 66)
  line L19 (-63, 50.1149) -> (-66, 50.1149)
  line L20 (-63, 30) -> (-63, 50.1149)
  line L21 (-66, 30) -> (-63, 30)
  line L22 (-66, 50.1149) -> (-66, 30)
  line L23 (-63, 19.9122) -> (-66, 19.9122)
  line L24 (-63, 0) -> (-63, 19.9122)
  line L25 (-66, 0) -> (-63, 0)
  line L26 (-66, 19.9122) -> (-66, 0)
  line L27 (66, 83) -> (63.0244, 83)
  line L28 (66, 62.9098) -> (66, 83)
  line L29 (63.0244, 62.9098) -> (66, 62.9098)
  line L30 (63.0244, 83) -> (63.0244, 62.9098)
  line L31 (66, 50.0527) -> (63.0244, 50.0527)
  line L32 (66, 29.9655) -> (66, 50.0527)
  line L33 (63.0244, 29.9655) -> (66, 29.9655)
  line L34 (63.0244, 50.0527) -> (63.0244, 29.9655)
  line L35 (66, 19.9734) -> (63.0244, 19.9734)
  line L36 (66, 0) -> (66, 19.9734)
  line L37 (63.0244, 0) -> (66, 0)
  line L38 (63.0244, 19.9734) -> (63.0244, 0)
  circle C1 centre (-61.5, 81.5) radius 2.15
  point P17 (-66, 77.9245)
  point P21 (-66, 50.1149)
  point P27 (-63, 0)
  point P25 (-66, 19.9122)
  point P31 (66, 62.9098)
  point P29 (63.0244, 83)
  point P35 (66, 29.9655)
  point P10 (66, 0)
  point P39 (66, 0)
  horizontal L15
  vertical L16
  horizontal L17
  vertical L18
  coincident L13 P17
  horizontal L19
  vertical L20
  horizontal L21
  vertical L22
  coincident L13 P21
  horizontal L23
  vertical L24
  horizontal L25
  vertical L26
  coincident L14 P27
  coincident L13 P25
  horizontal L27
  vertical L28
  horizontal L29
  vertical L30
  coincident L9 P31
  coincident L10 P29
  horizontal L31
  vertical L32
  horizontal L33
  vertical L34
  coincident L9 P35
  horizontal L35
  vertical L36
  horizontal L37
  vertical L38
  coincident P10 P39
extrude "拉伸20" cut sketch "草图17" profile of L8 L9 L10 L13 L14 L15 L16 L17 L18 L19 L20 L21 L22 L23 L24 L25 L26 L27 L28 L29 L30 L31 L32 L33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 against normal blind 3
combine "合并6"
combine "合并7"
combine "合并8"
extrude "拉伸21" new body sketch "草图17" profile of L8 L9 L10 L13 L14 L15 L16 L17 L18 L19 L20 L21 L22 L23 L24 L25 L26 L27 L28 L29 L30 L31 L32 L33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 against normal blind 3
combine "合并9"
combine "合并10"
sketch "草图18" plane through (0, 0, 83) normal (0, 0, 1) x axis (-1, 0, 0)
  line L1 (60, 154.5) -> (62.9999, 154.5)
  line L2 (60, 148.5) -> (60, 154.5)
  line L3 (-63, 148.5) -> (60, 148.5)
  line L4 (-63, 9.9866) -> (-63, 148.5)
  line L5 (-64, 9.9866) -> (-63, 9.9866)
  line L6 (-66, -8.0134) -> (-66, 7.9866)
  line L7 (-63, -10.0134) -> (-64, -10.0134)
  line L8 (-63, -148.5267) -> (-63, -10.0134)
  line L9 (59.9999, -148.5267) -> (-63, -148.5267)
  line L10 (59.9999, -153.5267) -> (59.9999, -148.5267)
  line L11 (62.9999, -153.5267) -> (59.9999, -153.5267)
  line L12 (62.9999, 154.5) -> (62.9999, -153.5267)
  line L13 (36.5, -73) -> (36.5, -47)
  line L14 (-36.5, -73) -> (36.5, -73)
  line L15 (-36.5, -47) -> (-36.5, -73)
  line L16 (36.5, -47) -> (-36.5, -47)
  line L17 (1.3407, 91.6748) -> (29.625, 119.959)
  line L18 (-26.9436, 119.959) -> (1.3407, 91.6748)
  line L19 (1200.8428, 190.8434) -> (201.4321, 190.8434)
  line L20 (1200.8428, -526.3808) -> (1200.8428, 190.8434)
  line L21 (201.4321, -526.3808) -> (1200.8428, -526.3808)
  line L22 (201.4321, 190.8434) -> (201.4321, -526.3808)
  arc A1 centre (-64, 7.9866) radius 2 clockwise from (-66, 7.9866) to (-64, 9.9866)
  arc A2 centre (-64, -8.0134) radius 2 clockwise from (-64, -10.0134) to (-66, -8.0134)
  circle C1 centre (20.0762, -102.4465) radius 6
  circle C2 centre (-20.9238, -102.4465) radius 6
  arc A3 centre (1.3407, 91.6748) radius 40 clockwise from (-26.9436, 119.959) to (29.625, 119.959)
  horizontal L19
  vertical L20
  horizontal L21
  vertical L22
extrude "拉伸22" new body sketch "草图18" profile of L19 L20 L21 L22 along normal blind 3
move "移动3"
copy_paste_bodies "复制和粘贴实体"
move "移动4"
move "移动5"
align "对齐1"
move "移动6"
align "对齐2"
align "对齐3"
align "对齐4"
align "对齐5"
move "移动7"
move "移动8"
move "移动9"
move "移动10"
move "移动11"
move "移动12"
move "移动13"
move "移动14"
move "移动15"
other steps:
base_feature "基础特征1"
base_feature "基础特征3"
create_component "创建零部件1"
create_component "创建零部件1"
remove_body "移除实体1"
